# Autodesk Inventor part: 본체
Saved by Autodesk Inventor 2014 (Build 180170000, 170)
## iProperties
Created: 2026-06
Part Number: 본체
Material: 알루미늄 6061
Document SubType Name: Modeling
Designer: dg
Density: 2.71 g/cm^3
Appearance: 알루미늄 - 평지
Author: jhkim
Creation Date: 2026-05-29
Sending System: Autodesk Inventor 2027
Preprocessor: ST-DEVELOPER v20.1
Author: dg
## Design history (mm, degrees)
node "본체1"
node "솔리드1"
node "기준1"
